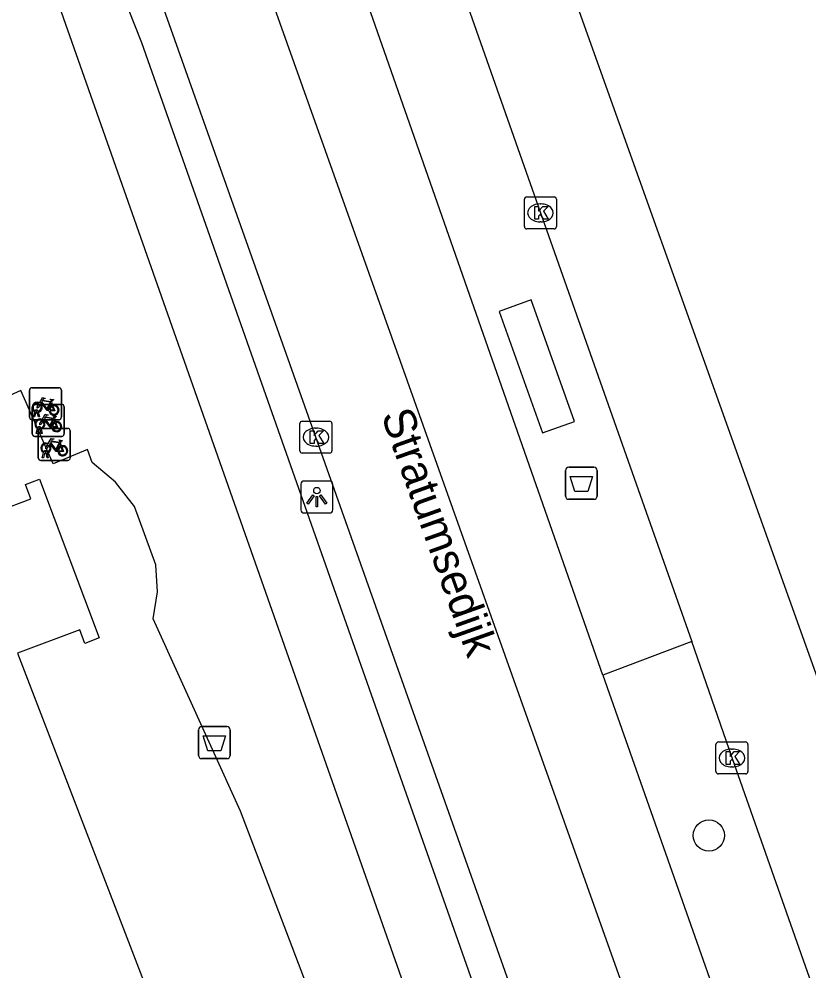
# Model space of a CAD drawing. Extents: x 161354 to 161876, y 382161 to 382804.
# Drawn here: x 161788.04 to 161812.75, y 382525.12 to 382554.88 of the extents above; entities that cross this region are included whole.
import ezdxf

# ---------------------------------------------------------------- set-up
doc = ezdxf.new("R2010")
doc.units = 0
for name, color, linetype in [('IMGEO_Afvalbak', 7, 'Continuous'), ('IMGEO_Boom', 7, 'Continuous'), ('IMGEO_Fietsenrek', 7, 'Continuous'), ('IMGEO_Fietspad_gesloten', 7, 'Continuous'), ('IMGEO_Kolk', 7, 'Continuous'), ('IMGEO_Lichtpunt', 7, 'Continuous'), ('IMGEO_Openbare_ruimte_label', 7, 'Continuous'), ('IMGEO_OVBaan_gesloten', 7, 'Continuous'), ('IMGEO_Pand', 7, 'Continuous'), ('IMGEO_Rijbaan_lokaal_gesloten', 7, 'Continuous'), ('IMGEO_Rijbaan_lokaal_open', 7, 'Continuous'), ('IMGEO_Voetpad_open', 7, 'Continuous')]:
    doc.layers.add(name, color=color, linetype=linetype)

msp = doc.modelspace()

# ---------------------------------------------------------------- linework, layer by layer
at = {"layer": 'IMGEO_Afvalbak'}
for p, q in [((161805.135, 382539.966), (161805.135, 382540.766)), ((161805.135, 382540.766), (161805.135, 382539.966)), ((161805.235, 382540.866), (161806.025, 382540.866)), ((161806.025, 382540.866), (161805.235, 382540.866)), ((161806.125, 382540.766), (161806.125, 382539.966)), ((161806.125, 382539.966), (161806.125, 382540.766)), ((161806.025, 382539.866), (161805.235, 382539.866)), ((161805.235, 382539.866), (161806.025, 382539.866)), ((161793.754, 382532.757), (161794.544, 382532.757)), ((161794.544, 382532.757), (161793.754, 382532.757)), ((161793.654, 382531.857), (161793.654, 382532.657)), ((161793.654, 382532.657), (161793.654, 382531.857)), ((161794.644, 382532.657), (161794.644, 382531.857)), ((161794.644, 382531.857), (161794.644, 382532.657)), ((161794.544, 382531.757), (161793.754, 382531.757)), ((161793.754, 382531.757), (161794.544, 382531.757))]:
    msp.add_line(p, q, dxfattribs=at)
for points in [[(161805.278, 382540.58), (161805.982, 382540.58), (161805.833, 382540.11), (161805.427, 382540.11), (161805.278, 382540.58)], [(161793.797, 382532.471), (161794.501, 382532.471), (161794.352, 382532.001), (161793.946, 382532.001), (161793.797, 382532.471)]]:
    msp.add_lwpolyline(points, dxfattribs=at)
for centre, start, end in [((161805.235, 382540.766), 90, 180), ((161805.235, 382540.766), 90, 180), ((161806.025, 382540.766), 0, 90), ((161806.025, 382540.766), 360, 90), ((161805.235, 382539.966), 180, 270), ((161805.235, 382539.966), 180, 270), ((161806.025, 382539.966), 270, 0), ((161806.025, 382539.966), 270, 0), ((161793.754, 382532.657), 90, 180), ((161793.754, 382532.657), 90, 180), ((161794.544, 382532.657), 0, 90), ((161794.544, 382532.657), 360, 90), ((161793.754, 382531.857), 180, 270), ((161793.754, 382531.857), 180, 270), ((161794.544, 382531.857), 270, 0), ((161794.544, 382531.857), 270, 0)]:
    msp.add_arc(centre, 0.1, start, end, dxfattribs=at)
at = {"layer": 'IMGEO_Boom'}
msp.add_circle((161809.62, 382529.355), 0.489, dxfattribs=at)
at = {"layer": 'IMGEO_Fietsenrek'}
for p, q in [((161788.368, 382542.43), (161788.368, 382543.271)), ((161788.368, 382543.271), (161788.368, 382542.43)), ((161788.443, 382543.355), (161789.284, 382543.355)), ((161789.284, 382543.355), (161788.443, 382543.355)), ((161789.368, 382543.28), (161789.368, 382542.439)), ((161789.368, 382542.439), (161789.368, 382543.28)), ((161788.53, 382542.834), (161789.371, 382542.834)), ((161789.371, 382542.834), (161788.53, 382542.834)), ((161789.055, 382542.904), (161789.091, 382542.809)), ((161788.455, 382541.909), (161788.455, 382542.75)), ((161788.455, 382542.75), (161788.455, 382541.909)), ((161788.495, 382542.439), (161788.534, 382542.599)), ((161788.564, 382542.587), (161788.529, 382542.439)), ((161788.606, 382542.611), (161788.605, 382542.615)), ((161788.647, 382542.439), (161788.613, 382542.581)), ((161788.637, 382542.622), (161788.638, 382542.615)), ((161788.645, 382542.585), (161788.68, 382542.439)), ((161789.455, 382542.759), (161789.455, 382541.918)), ((161789.455, 382541.918), (161789.455, 382542.759)), ((161789.293, 382542.355), (161788.452, 382542.355)), ((161788.452, 382542.355), (161789.293, 382542.355)), ((161788.529, 382542.439), (161788.495, 382542.439)), ((161788.68, 382542.439), (161788.647, 382542.439)), ((161789.142, 382542.383), (161789.178, 382542.288)), ((161788.582, 382541.918), (161788.621, 382542.078)), ((161788.616, 382541.918), (161788.582, 382541.918)), ((161788.651, 382542.066), (161788.616, 382541.918)), ((161788.642, 382541.156), (161788.642, 382541.997)), ((161788.642, 382541.997), (161788.642, 382541.156)), ((161788.693, 382542.09), (161788.692, 382542.094)), ((161788.734, 382541.918), (161788.7, 382542.06)), ((161788.717, 382542.081), (161789.558, 382542.081)), ((161789.558, 382542.081), (161788.717, 382542.081)), ((161788.724, 382542.101), (161788.725, 382542.094)), ((161788.732, 382542.064), (161788.767, 382541.918)), ((161788.767, 382541.918), (161788.734, 382541.918)), ((161789.642, 382542.006), (161789.642, 382541.165)), ((161789.642, 382541.165), (161789.642, 382542.006)), ((161789.38, 382541.834), (161788.539, 382541.834)), ((161788.539, 382541.834), (161789.38, 382541.834)), ((161789.329, 382541.63), (161789.365, 382541.535)), ((161788.769, 382541.165), (161788.808, 382541.325)), ((161788.838, 382541.313), (161788.803, 382541.165)), ((161788.88, 382541.337), (161788.879, 382541.341)), ((161788.921, 382541.165), (161788.887, 382541.307)), ((161788.911, 382541.348), (161788.912, 382541.341)), ((161788.919, 382541.311), (161788.954, 382541.165)), ((161789.567, 382541.081), (161788.726, 382541.081)), ((161788.726, 382541.081), (161789.567, 382541.081)), ((161788.803, 382541.165), (161788.769, 382541.165)), ((161788.954, 382541.165), (161788.921, 382541.165))]:
    msp.add_line(p, q, dxfattribs=at)
for points in [[(161788.702, 382542.829), (161788.65, 382542.739), (161788.61, 382542.714), (161788.611, 382542.761), (161788.666, 382542.855)], [(161788.681, 382542.881), (161788.776, 382543.045), (161788.862, 382543.031), (161788.864, 382543.022), (161788.808, 382543.011), (161788.781, 382542.966), (161789.037, 382542.925)], [(161788.977, 382542.637), (161788.927, 382542.637), (161788.736, 382542.888), (161788.717, 382542.856)], [(161789.024, 382542.9), (161788.767, 382542.941), (161788.75, 382542.912), (161788.917, 382542.692), (161789.024, 382542.9)], [(161789.072, 382542.802), (161789.042, 382542.879), (161788.933, 382542.661), (161788.976, 382542.661)], [(161789.037, 382542.925), (161789.062, 382542.974), (161789.056, 382542.978), (161789.033, 382542.982), (161789.021, 382542.989), (161789.02, 382542.992), (161789.022, 382542.997), (161789.117, 382542.982), (161789.119, 382542.972), (161789.109, 382542.959), (161789.097, 382542.953), (161789.083, 382542.959), (161789.055, 382542.904)], [(161788.768, 382542.36), (161788.863, 382542.524), (161788.949, 382542.51), (161788.951, 382542.501), (161788.895, 382542.49), (161788.868, 382542.445), (161789.124, 382542.404)], [(161789.006, 382542.661), (161789.126, 382542.66), (161789.082, 382542.774)], [(161789.102, 382542.781), (161789.157, 382542.636), (161789.007, 382542.636)], [(161788.789, 382542.308), (161788.737, 382542.218), (161788.697, 382542.193), (161788.698, 382542.24), (161788.753, 382542.334)], [(161789.064, 382542.116), (161789.014, 382542.116), (161788.823, 382542.367), (161788.804, 382542.335)], [(161789.111, 382542.379), (161788.854, 382542.42), (161788.837, 382542.391), (161789.004, 382542.171), (161789.111, 382542.379)], [(161789.159, 382542.281), (161789.129, 382542.358), (161789.02, 382542.14), (161789.063, 382542.14)], [(161789.093, 382542.14), (161789.213, 382542.139), (161789.169, 382542.253)], [(161789.189, 382542.26), (161789.244, 382542.115), (161789.094, 382542.115)], [(161789.124, 382542.404), (161789.149, 382542.453), (161789.143, 382542.457), (161789.12, 382542.461), (161789.108, 382542.468), (161789.107, 382542.471), (161789.109, 382542.476), (161789.204, 382542.461), (161789.206, 382542.451), (161789.196, 382542.438), (161789.184, 382542.432), (161789.17, 382542.438), (161789.142, 382542.383)], [(161788.955, 382541.607), (161789.05, 382541.771), (161789.136, 382541.757), (161789.138, 382541.748), (161789.082, 382541.737), (161789.055, 382541.692), (161789.311, 382541.651)], [(161789.251, 382541.363), (161789.201, 382541.363), (161789.01, 382541.614), (161788.991, 382541.582)], [(161789.298, 382541.626), (161789.041, 382541.667), (161789.024, 382541.638), (161789.191, 382541.418), (161789.298, 382541.626)], [(161789.346, 382541.528), (161789.316, 382541.605), (161789.207, 382541.387), (161789.25, 382541.387)], [(161789.311, 382541.651), (161789.336, 382541.7), (161789.33, 382541.704), (161789.307, 382541.708), (161789.295, 382541.715), (161789.294, 382541.718), (161789.296, 382541.723), (161789.391, 382541.708), (161789.393, 382541.698), (161789.383, 382541.685), (161789.371, 382541.679), (161789.357, 382541.685), (161789.329, 382541.63)], [(161788.976, 382541.555), (161788.924, 382541.465), (161788.884, 382541.44), (161788.885, 382541.487), (161788.94, 382541.581)], [(161789.28, 382541.387), (161789.4, 382541.386), (161789.356, 382541.5)], [(161789.376, 382541.507), (161789.431, 382541.362), (161789.281, 382541.362)]]:
    msp.add_lwpolyline(points, dxfattribs=at)
for centre, radius, start, end in [((161788.446, 382543.277), 0.0779, 92.4484, 184.2845), ((161788.446, 382543.277), 0.0779, 92.4484, 184.2845), ((161789.29, 382543.277), 0.0779, 2.4484, 94.2845), ((161789.29, 382543.277), 0.0779, 2.4484, 94.2845), ((161788.608, 382542.74), 0.159, 62.6766, 242.1369), ((161788.533, 382542.756), 0.0779, 92.4484, 184.2845), ((161788.533, 382542.756), 0.0779, 92.4484, 184.2845), ((161788.608, 382542.74), 0.129, 63.3192, 238.903), ((161788.608, 382542.74), 0.129, 283.6043, 43.4302), ((161788.608, 382542.74), 0.159, 283.5766, 46.6042), ((161789.135, 382542.656), 0.159, 113.3408, 178.3217), ((161789.135, 382542.656), 0.159, 187.0065, 105.7708), ((161789.135, 382542.656), 0.129, 188.6715, 104.5883), ((161789.377, 382542.756), 0.0779, 2.4484, 94.2845), ((161789.377, 382542.756), 0.0779, 2.4484, 94.2845), ((161788.588, 382542.611), 0.0499, 12.8025, 158.6934), ((161788.608, 382542.74), 0.159, 253.9967, 271.7867), ((161788.588, 382542.611), 0.0174, 12.8025, 163.4502), ((161788.608, 382542.74), 0.129, 253.415, 269.0204), ((161789.135, 382542.656), 0.129, 113.923, 177.9556), ((161788.446, 382542.433), 0.0779, 182.4484, 274.2845), ((161788.446, 382542.433), 0.0779, 182.4484, 274.2845), ((161788.695, 382542.219), 0.159, 62.6766, 242.1369), ((161788.695, 382542.219), 0.129, 63.3192, 238.903), ((161788.695, 382542.219), 0.129, 283.6043, 43.4302), ((161788.695, 382542.219), 0.159, 283.5766, 46.6042), ((161789.222, 382542.135), 0.159, 113.3408, 178.3217), ((161789.222, 382542.135), 0.159, 187.0065, 105.7708), ((161789.222, 382542.135), 0.129, 113.923, 177.9556), ((161789.222, 382542.135), 0.129, 188.6715, 104.5883), ((161789.29, 382542.433), 0.0779, 272.4484, 4.2845), ((161789.29, 382542.433), 0.0779, 272.4484, 4.2845), ((161788.533, 382541.912), 0.0779, 182.4484, 274.2845), ((161788.533, 382541.912), 0.0779, 182.4484, 274.2845), ((161788.675, 382542.09), 0.0499, 12.8025, 158.6934), ((161788.72, 382542.003), 0.0779, 92.4484, 184.2845), ((161788.72, 382542.003), 0.0779, 92.4484, 184.2845), ((161788.695, 382542.219), 0.159, 253.9967, 271.7867), ((161788.675, 382542.09), 0.0174, 12.8025, 163.4502), ((161788.695, 382542.219), 0.129, 253.415, 269.0204), ((161789.377, 382541.912), 0.0779, 272.4484, 4.2845), ((161789.377, 382541.912), 0.0779, 272.4484, 4.2845), ((161789.564, 382542.003), 0.0779, 2.4484, 94.2845), ((161789.564, 382542.003), 0.0779, 2.4484, 94.2845), ((161788.882, 382541.466), 0.159, 62.6766, 242.1369), ((161788.882, 382541.466), 0.129, 63.3192, 238.903), ((161788.862, 382541.337), 0.0499, 12.8025, 158.6934), ((161788.882, 382541.466), 0.159, 253.9967, 271.7867), ((161788.862, 382541.337), 0.0174, 12.8025, 163.4502), ((161788.882, 382541.466), 0.129, 253.415, 269.0204), ((161788.882, 382541.466), 0.129, 283.6043, 43.4302), ((161788.882, 382541.466), 0.159, 283.5766, 46.6042), ((161789.409, 382541.382), 0.159, 113.3408, 178.3217), ((161789.409, 382541.382), 0.159, 187.0065, 105.7708), ((161789.409, 382541.382), 0.129, 113.923, 177.9556), ((161789.409, 382541.382), 0.129, 188.6715, 104.5883), ((161788.72, 382541.159), 0.0779, 182.4484, 274.2845), ((161788.72, 382541.159), 0.0779, 182.4484, 274.2845), ((161789.564, 382541.159), 0.0779, 272.4484, 4.2845), ((161789.564, 382541.159), 0.0779, 272.4484, 4.2845)]:
    msp.add_arc(centre, radius, start, end, dxfattribs=at)
at = {"layer": 'IMGEO_Fietspad_gesloten'}
for points in [[(161791.037, 382556.261), (161791.875, 382554.154), (161809.536, 382504.029), (161810.816, 382500)], [(161804.957, 382510.847), (161789.046, 382556.024)]]:
    msp.add_lwpolyline(points, dxfattribs=at)
at = {"layer": 'IMGEO_Kolk'}
for p, q in [((161803.849, 382548.395), (161803.849, 382549.247)), ((161803.924, 382549.321), (161804.776, 382549.321)), ((161804.337, 382549.101), (161804.362, 382549.101)), ((161804.85, 382549.247), (161804.85, 382548.395)), ((161804.36, 382548.541), (161804.335, 382548.541)), ((161804.776, 382548.321), (161803.924, 382548.321)), ((161796.828, 382541.383), (161796.828, 382542.235)), ((161796.903, 382542.309), (161797.755, 382542.309)), ((161797.829, 382542.235), (161797.829, 382541.383)), ((161797.316, 382542.089), (161797.341, 382542.089)), ((161797.755, 382541.309), (161796.903, 382541.309)), ((161797.339, 382541.529), (161797.314, 382541.529)), ((161809.84, 382531.351), (161809.84, 382532.203)), ((161809.915, 382532.277), (161810.767, 382532.277)), ((161810.841, 382532.203), (161810.841, 382531.351)), ((161810.328, 382532.057), (161810.353, 382532.057)), ((161810.351, 382531.497), (161810.326, 382531.497)), ((161810.767, 382531.277), (161809.915, 382531.277))]:
    msp.add_line(p, q, dxfattribs=at)
for points in [[(161803.849, 382548.395), (161803.849, 382549.247)], [(161803.924, 382549.321), (161804.776, 382549.321)], [(161804.85, 382549.247), (161804.85, 382548.395)], [(161804.17, 382549.021), (161804.293, 382549.021), (161804.293, 382548.87), (161804.423, 382549.021), (161804.587, 382549.021), (161804.441, 382548.87), (161804.594, 382548.621), (161804.442, 382548.621), (161804.357, 382548.785), (161804.293, 382548.718), (161804.293, 382548.621), (161804.17, 382548.621), (161804.17, 382549.021)], [(161804.776, 382548.321), (161803.924, 382548.321)], [(161796.828, 382541.383), (161796.828, 382542.235)], [(161796.903, 382542.309), (161797.755, 382542.309)], [(161797.829, 382542.235), (161797.829, 382541.383)], [(161797.149, 382542.009), (161797.272, 382542.009), (161797.272, 382541.858), (161797.402, 382542.009), (161797.566, 382542.009), (161797.42, 382541.858), (161797.573, 382541.609), (161797.421, 382541.609), (161797.336, 382541.773), (161797.272, 382541.706), (161797.272, 382541.609), (161797.149, 382541.609), (161797.149, 382542.009)], [(161797.755, 382541.309), (161796.903, 382541.309)], [(161809.84, 382531.351), (161809.84, 382532.203)], [(161809.915, 382532.277), (161810.767, 382532.277)], [(161810.841, 382532.203), (161810.841, 382531.351)], [(161810.161, 382531.977), (161810.284, 382531.977), (161810.284, 382531.826), (161810.414, 382531.977), (161810.578, 382531.977), (161810.432, 382531.826), (161810.585, 382531.577), (161810.433, 382531.577), (161810.348, 382531.741), (161810.284, 382531.674), (161810.284, 382531.577), (161810.161, 382531.577), (161810.161, 382531.977)], [(161810.767, 382531.277), (161809.915, 382531.277)]]:
    msp.add_lwpolyline(points, dxfattribs=at)
for centre, start, end in [((161803.926, 382549.245), 91.552, 178.448), ((161803.926, 382549.245), 91.552, 178.448), ((161804.774, 382549.245), 1.552, 88.448), ((161804.774, 382549.245), 1.552, 88.448), ((161803.926, 382548.397), 181.552, 268.448), ((161803.926, 382548.397), 181.552, 268.448), ((161804.774, 382548.397), 271.552, 358.448), ((161804.774, 382548.397), 271.552, 358.448), ((161796.905, 382542.233), 91.552, 178.448), ((161796.905, 382542.233), 91.552, 178.448), ((161797.753, 382542.233), 1.552, 88.448), ((161797.753, 382542.233), 1.552, 88.448), ((161796.905, 382541.385), 181.552, 268.448), ((161796.905, 382541.385), 181.552, 268.448), ((161797.753, 382541.385), 271.552, 358.448), ((161797.753, 382541.385), 271.552, 358.448), ((161809.917, 382532.201), 91.552, 178.448), ((161809.917, 382532.201), 91.552, 178.448), ((161810.765, 382532.201), 1.552, 88.448), ((161810.765, 382532.201), 1.552, 88.448), ((161809.917, 382531.353), 181.552, 268.448), ((161809.917, 382531.353), 181.552, 268.448), ((161810.765, 382531.353), 271.552, 358.448), ((161810.765, 382531.353), 271.552, 358.448)]:
    msp.add_arc(centre, 0.0765, start, end, dxfattribs=at)
for centre, major_axis, ratio, start_param, end_param in [((161804.336, 382548.821), (-0.387, 0.002), 0.722429, 4.712389, 7.853982), ((161804.361, 382548.821), (-0.39, 0.002), 0.717154, 1.570796, 4.712389), ((161797.315, 382541.809), (-0.387, 0.002), 0.722429, 4.712389, 7.853982), ((161797.34, 382541.809), (-0.39, 0.002), 0.717154, 1.570796, 4.712389), ((161810.327, 382531.777), (-0.387, 0.002), 0.722429, 4.712389, 7.853982), ((161810.352, 382531.777), (-0.39, 0.002), 0.717154, 1.570796, 4.712389)]:
    msp.add_ellipse(centre, major_axis=major_axis, ratio=ratio, start_param=start_param, end_param=end_param, dxfattribs=at)
at = {"layer": 'IMGEO_Lichtpunt'}
for p, q in [((161797.761, 382540.435), (161796.953, 382540.435)), ((161797.761, 382540.435), (161796.953, 382540.435)), ((161796.859, 382540.34), (161796.859, 382539.533)), ((161796.859, 382540.34), (161796.859, 382539.533)), ((161797.855, 382539.533), (161797.855, 382540.34)), ((161797.855, 382539.533), (161797.855, 382540.34)), ((161796.953, 382539.439), (161797.761, 382539.439)), ((161796.953, 382539.439), (161797.761, 382539.439))]:
    msp.add_line(p, q, dxfattribs=at)
for points in [[(161797.233, 382540.004), (161797.272, 382539.976), (161797.084, 382539.714), (161797.046, 382539.741), (161797.233, 382540.004)], [(161797.335, 382539.956), (161797.382, 382539.956), (161797.382, 382539.634), (161797.335, 382539.634), (161797.335, 382539.956)], [(161797.445, 382539.976), (161797.483, 382540.003), (161797.67, 382539.741), (161797.631, 382539.713), (161797.445, 382539.976)]]:
    msp.add_lwpolyline(points, dxfattribs=at)
msp.add_circle((161797.358, 382540.138), 0.0994, dxfattribs=at)
for centre, start, end in [((161796.953, 382540.34), 90, 180), ((161796.953, 382540.34), 90, 180), ((161797.761, 382540.34), 0, 90), ((161797.761, 382540.34), 0, 90), ((161796.953, 382539.533), 180, 270), ((161796.953, 382539.533), 180, 270), ((161797.761, 382539.533), 270, 0), ((161797.761, 382539.533), 270, 360)]:
    msp.add_arc(centre, 0.0946, start, end, dxfattribs=at)
at = {"layer": 'IMGEO_OVBaan_gesloten'}
for points in [[(161802.764, 382562.95), (161813.473, 382532.981), (161825.781, 382496.935), (161846.541, 382430.889), (161855.809, 382400.479), (161858.997, 382388.612), (161866.559, 382360.242), (161870.464, 382345.086)], [(161799.758, 382561.881), (161804.351, 382548.821), (161809.081, 382535.415)], [(161867.15, 382344.369), (161863.03, 382359.905), (161858.62, 382376.824), (161853.632, 382395.674), (161853.29, 382396.854), (161849.368, 382410.334), (161848.992, 382411.495), (161838.414, 382445.861), (161832.947, 382463.543), (161827.474, 382481.211), (161827.11, 382482.403), (161824.596, 382490.14), (161822.084, 382497.878), (161821.393, 382500), (161816.691, 382513.676), (161816.31, 382514.849), (161810.342, 382531.777), (161809.081, 382535.415)]]:
    msp.add_lwpolyline(points, dxfattribs=at)
at = {"layer": 'IMGEO_Pand'}
msp.add_lwpolyline([(161756.431, 382531.707), (161757.391, 382529.312), (161765.137, 382532.22), (161764.271, 382534.527), (161785.178, 382542.374), (161786.424, 382539.134), (161788.413, 382539.88), (161788.244, 382540.331), (161788.686, 382540.497), (161790.549, 382535.529), (161790.101, 382535.361), (161789.941, 382535.787), (161787.992, 382535.056), (161795.715, 382514.974)], dxfattribs=at)
at = {"layer": 'IMGEO_Rijbaan_lokaal_gesloten'}
for points in [[(161806.297, 382534.364), (161796.666, 382561.875)], [(161794.072, 382560.74), (161807.929, 382521.82), (161816.118, 382497.6), (161820.737, 382483.038), (161830.884, 382450.092), (161838.155, 382424.383), (161849.904, 382380.752), (161850.34, 382378.969), (161857.915, 382347.985), (161859.586, 382342.023)], [(161816.438, 382486.046), (161811.913, 382500), (161811.234, 382502.093), (161810.418, 382504.506), (161803.828, 382523.451), (161797.329, 382541.81), (161791.147, 382559.234), (161791.133, 382559.453)], [(161806.297, 382534.364), (161814.219, 382511.898), (161817.462, 382502.267), (161818.198, 382499.999), (161826.049, 382475.724)]]:
    msp.add_lwpolyline(points, dxfattribs=at)
at = {"layer": 'IMGEO_Rijbaan_lokaal_open'}
for points in [[(161805.411, 382542.293), (161804.057, 382546.1), (161803.063, 382545.735), (161804.416, 382541.943), (161805.411, 382542.293)], [(161809.081, 382535.415), (161806.297, 382534.364)]]:
    msp.add_lwpolyline(points, dxfattribs=at)
at = {"layer": 'IMGEO_Voetpad_open'}
msp.add_lwpolyline([(161801.747, 382512.319), (161794.971, 382530.118), (161792.241, 382536.131), (161792.378, 382536.972), (161792.323, 382537.821), (161791.654, 382539.638), (161791.061, 382540.405), (161790.328, 382541.011), (161790.189, 382541.423), (161789.107, 382540.979), (161788.094, 382543.265), (161787.424, 382542.968), (161782.001, 382556.605)], dxfattribs=at)

# ---------------------------------------------------------------- texts
at = {"layer": 'IMGEO_Openbare_ruimte_label'}
msp.add_text('Stratumsedijk', height=1, rotation=289.6307, dxfattribs=at).set_placement((161799.36, 382542.499))

doc.saveas('drawing.dxf')
